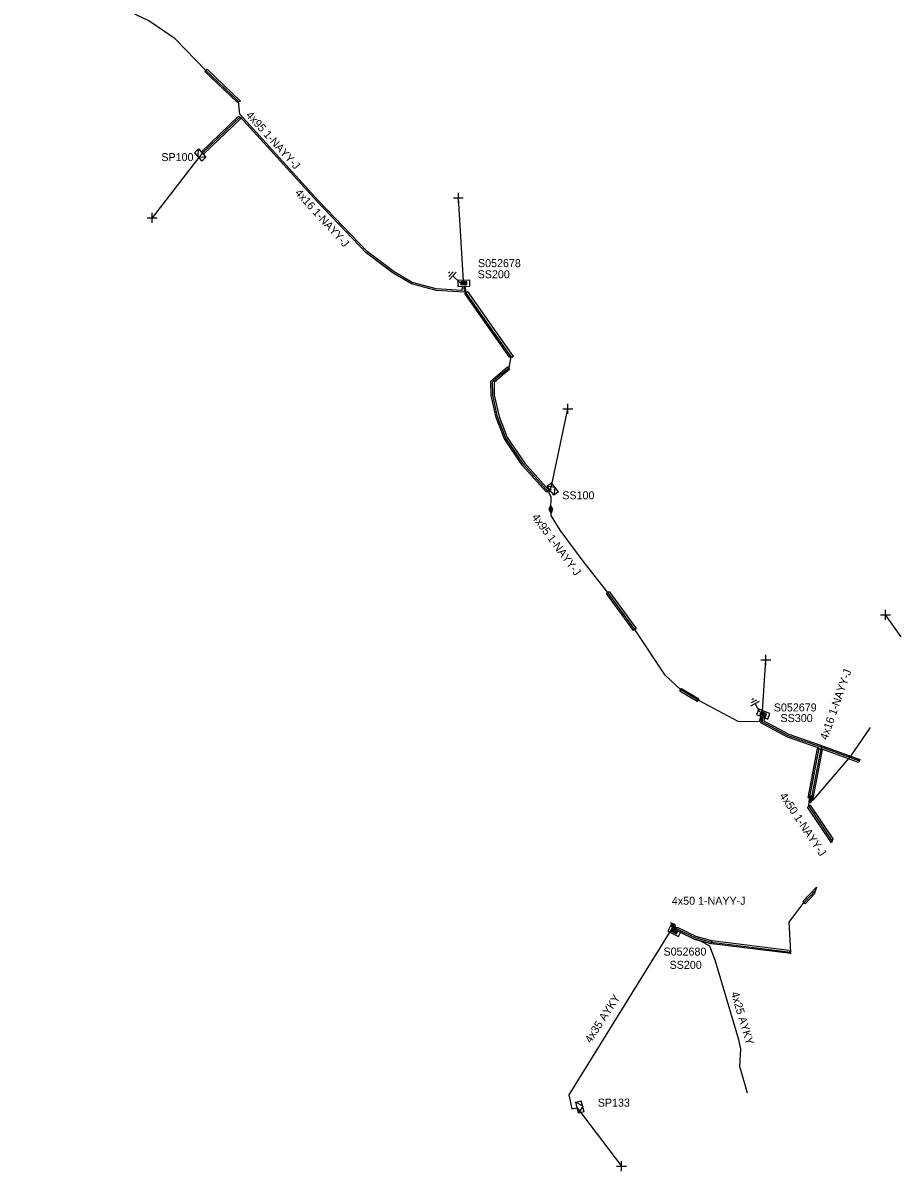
# Model space of a CAD drawing. Extents: x -717562 to -713845, y -1151196 to -1143903.
# Drawn here: x -714923 to -714813.3, y -1150441.1 to -1150297.7 of the extents above; entities that cross this region are included whole.
import ezdxf

# ---------------------------------------------------------------- set-up
doc = ezdxf.new("R2010")
doc.units = 0
for name, color, linetype in [('Vrstva 1', 7, 'Continuous'), ('Vrstva 14', 7, 'Continuous'), ('Vrstva 15', 7, 'Continuous'), ('Vrstva 19', 7, 'Continuous'), ('Vrstva 20', 7, 'Continuous'), ('Vrstva 28', 7, 'Continuous'), ('Vrstva 29', 7, 'Continuous'), ('Vrstva 30', 7, 'Continuous'), ('Vrstva 31', 7, 'Continuous'), ('Vrstva 33', 7, 'Continuous'), ('Vrstva 34', 7, 'Continuous'), ('Vrstva 4', 7, 'Continuous'), ('Vrstva 5', 7, 'Continuous'), ('Vrstva 52', 7, 'Continuous'), ('Vrstva 54', 7, 'Continuous'), ('Vrstva 59', 7, 'Continuous'), ('Vrstva 6', 7, 'Continuous'), ('Vrstva 8', 7, 'Continuous'), ('Vrstva 9', 7, 'Continuous')]:
    doc.layers.add(name, color=color, linetype=linetype)

# ---------------------------------------------------------------- blocks, each defined once
blk = doc.blocks.new('NN870')
at = {"layer": 'Vrstva 4'}
for points in [[(0, -0.25), (0.5, 0), (0, 0.25), (-0.5, 0), (0, -0.25)], [(0.37, 0), (0, 0.19), (-0.36, 0), (0, -0.19), (0.37, 0)], [(0.24, 0), (0, 0.12), (-0.25, 0), (0, -0.12), (0.24, 0)], [(0.12, 0), (0, 0.06), (-0.13, 0), (0, -0.06), (0.12, 0)]]:
    blk.add_lwpolyline(points, dxfattribs=at)
blk = doc.blocks.new('NN800')
at = {"layer": 'Vrstva 1'}
for points in [[(-0.44, 0.44), (0.44, -0.44)], [(-0.44, -0.44), (0.44, 0.44)]]:
    blk.add_lwpolyline(points, dxfattribs=at)
blk = doc.blocks.new('NN620')
at = {"layer": 'Vrstva 8'}
for points in [[(0.75, 0), (-0.75, 0)], [(-0.75, 0), (-0.75, -0.75)], [(0.75, -0.75), (0.75, 0)], [(-0.75, -0.75), (0.75, -0.75)], [(0.37, -0.18), (-0.38, -0.18)], [(-0.38, -0.18), (-0.38, -0.56)], [(-0.38, -0.56), (0.37, -0.56)], [(0.32, -0.23), (-0.33, -0.23)], [(-0.33, -0.23), (-0.33, -0.51)], [(-0.33, -0.51), (0.32, -0.51)], [(0.27, -0.27), (-0.28, -0.27)], [(-0.28, -0.27), (-0.28, -0.46)], [(-0.28, -0.46), (0.27, -0.46)], [(0.23, -0.32), (-0.23, -0.32)], [(-0.23, -0.32), (-0.23, -0.42)], [(-0.23, -0.42), (0.23, -0.42)], [(-0.19, -0.37), (0.19, -0.37)], [(0.23, -0.42), (0.23, -0.32)], [(0.27, -0.46), (0.27, -0.27)], [(0.32, -0.51), (0.32, -0.23)], [(0.37, -0.56), (0.37, -0.18)]]:
    blk.add_lwpolyline(points, dxfattribs=at)
blk = doc.blocks.new('NN630')
at = {"layer": 'Vrstva 9'}
for points in [[(0, -0.7), (-0.7, 0)], [(-0.7, -0.7), (-0.7, 0), (0.7, 0), (0.7, -0.7)], [(-0.7, -0.7), (0.7, -0.7)], [(0, -0.7), (0.7, 0)]]:
    blk.add_lwpolyline(points, dxfattribs=at)
blk = doc.blocks.new('NN810')
at = {"layer": 'Vrstva 14'}
for points in [[(0, -0.64), (0, -1.89)], [(0.63, -1.89), (-0.62, -1.89)], [(0.39, -2.2), (-0.4, -2.2)], [(0, -2.52), (-0.12, -2.52)], [(0.14, -2.52), (0, -2.52)]]:
    blk.add_lwpolyline(points, dxfattribs=at)

msp = doc.modelspace()

# ---------------------------------------------------------------- linework, layer by layer
at = {"layer": 'Vrstva 20'}
for points in [[(-714896.28, -1150307.57), (-714900.31, -1150303.72), (-714900.03, -1150303.43), (-714895.9, -1150307.39), (-714895.89, -1150307.46)], [(-714900.49, -1150314.06), (-714900.77, -1150313.78), (-714896.11, -1150309.31), (-714895.83, -1150309.6)], [(-714861.81, -1150339.42), (-714862.22, -1150339.42), (-714867.83, -1150331.45), (-714867.5, -1150331.22), (-714861.8, -1150339.33)], [(-714857.62, -1150356.29), (-714860.66, -1150352.91), (-714862.87, -1150349.62), (-714863.92, -1150346.95), (-714864.54, -1150344.19), (-714864.57, -1150342.41), (-714863.36, -1150341.37), (-714862.47, -1150340.64), (-714862.22, -1150340.95), (-714863.1, -1150341.67), (-714864.17, -1150342.59), (-714864.14, -1150344.15), (-714863.54, -1150346.83), (-714862.51, -1150349.44), (-714860.34, -1150352.67), (-714857.36, -1150355.98)], [(-714846.73, -1150373.56), (-714850.1, -1150368.94), (-714849.78, -1150368.7), (-714846.41, -1150373.33)], [(-714838.57, -1150382.1), (-714838.77, -1150382.44), (-714840.95, -1150381.15), (-714840.75, -1150380.81)], [(-714824.33, -1150394.58), (-714824.91, -1150394.47), (-714823.74, -1150388.32), (-714823.15, -1150388.43)], [(-714818.61, -1150390.06), (-714823.3, -1150388.37), (-714823.16, -1150388), (-714818.48, -1150389.69)], [(-714821.99, -1150400.09), (-714824.98, -1150395.65), (-714824.65, -1150395.42), (-714821.83, -1150399.62)], [(-714823.86, -1150405.63), (-714824.17, -1150406.54), (-714825.29, -1150407.73), (-714825.58, -1150407.46)], [(-714836.98, -1150412.32), (-714837.05, -1150412.72), (-714837.06, -1150412.72), (-714839.11, -1150412.14), (-714841.45, -1150411.03), (-714841.28, -1150410.67), (-714838.97, -1150411.76)], [(-714827.1, -1150413.96), (-714836.96, -1150412.73), (-714836.91, -1150412.33), (-714827.29, -1150413.53)]]:
    msp.add_lwpolyline(points, close=True, dxfattribs=at)
at = {"layer": 'Vrstva 5'}
for points in [[(-714868.14, -1150330.54), (-714868.18, -1150331.09), (-714871.39, -1150330.89), (-714874.42, -1150330.07), (-714876.67, -1150328.74), (-714880.02, -1150326.23), (-714886.1, -1150319.88), (-714895.94, -1150309.07), (-714896.09, -1150307.48), (-714900.21, -1150303.54), (-714904, -1150299.64), (-714907.29, -1150297.39), (-714912.07, -1150295.14), (-714918.82, -1150292.96), (-714923.04, -1150291.75)], [(-714830.83, -1150384.28), (-714831.02, -1150385), (-714833.65, -1150384.96), (-714838.67, -1150382.27), (-714840.88, -1150380.96), (-714842.77, -1150379.16), (-714846.57, -1150373.45), (-714849.94, -1150368.82), (-714852.91, -1150365.09), (-714855.9, -1150361.04), (-714857.03, -1150359.19), (-714857.09, -1150358.45), (-714857.02, -1150356.89), (-714857.32, -1150356.33), (-714857.11, -1150356.11), (-714857.43, -1150356.21), (-714860.5, -1150352.79), (-714862.69, -1150349.53), (-714863.73, -1150346.89), (-714864.34, -1150344.17), (-714864.37, -1150342.5), (-714863.23, -1150341.52), (-714862.29, -1150340.75), (-714862.01, -1150339.38), (-714867.68, -1150331.32), (-714867.75, -1150330.5)], [(-714821.91, -1150399.86), (-714824.85, -1150395.48), (-714824.73, -1150394.57), (-714823.53, -1150388.29), (-714827.48, -1150386.9), (-714830.85, -1150385.12), (-714830.67, -1150384.37)], [(-714818.55, -1150389.87), (-714823.49, -1150388.09), (-714827.4, -1150386.72), (-714830.65, -1150385), (-714830.53, -1150384.41)], [(-714830.39, -1150384.46), (-714830.47, -1150384.87), (-714827.32, -1150386.54), (-714823.26, -1150387.96), (-714824.53, -1150394.6)], [(-714841.16, -1150410.95), (-714839.04, -1150411.95), (-714837.02, -1150412.52), (-714827.08, -1150413.76), (-714827.3, -1150410.03), (-714825.54, -1150407.71), (-714824.01, -1150406.08)], [(-714841.59, -1150410.76), (-714841.58, -1150410.67), (-714841.76, -1150410.47)]]:
    msp.add_lwpolyline(points, dxfattribs=at)
at = {"layer": 'Vrstva 52'}
for points in [[(-714867.94, -1150330.55), (-714867.9, -1150331.31), (-714871.42, -1150331.09), (-714874.5, -1150330.26), (-714876.78, -1150328.91), (-714880.15, -1150326.38), (-714886.25, -1150320.02), (-714895.91, -1150309.4), (-714900.63, -1150313.92)], [(-714824.53, -1150394.6), (-714824.25, -1150394.74), (-714819.58, -1150389.29), (-714817.13, -1150385.68)], [(-714841.76, -1150410.47), (-714854.82, -1150431.6), (-714854.46, -1150433.36), (-714853.77, -1150433.21)], [(-714840.92, -1150411.28), (-714839.05, -1150412.17), (-714838.37, -1150412.36), (-714837.26, -1150412.98), (-714836.54, -1150414.85), (-714833.62, -1150424.69), (-714833.39, -1150425.88), (-714833.5, -1150428.03), (-714832.54, -1150431.36)]]:
    msp.add_lwpolyline(points, dxfattribs=at)
at = {"layer": 'Vrstva 59'}
for points in [[(-714900.63, -1150313.92), (-714906.88, -1150322)], [(-714867.98, -1150329.87), (-714868.63, -1150319.5)], [(-714857.11, -1150356.11), (-714854.94, -1150345.88)], [(-714813.31, -1150374.35), (-714815.25, -1150371.63)], [(-714830.62, -1150383.64), (-714830.19, -1150377.25)], [(-714853.77, -1150433.21), (-714848.25, -1150440.5)]]:
    msp.add_lwpolyline(points, dxfattribs=at)

# ---------------------------------------------------------------- block references
at = {"layer": 'Vrstva 15'}
for p, rotation in [((-714867.94, -1150330.55), -133.1741162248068), ((-714830.67, -1150384.37), -152.94376550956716)]:
    msp.add_blockref('NN810', p, dxfattribs=dict(at, rotation=rotation))
at = {"layer": 'Vrstva 19'}
for p, rotation in [((-714857.09, -1150358.45), -85.36453611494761), ((-714824.53, -1150394.6), 79.17845832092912), ((-714841.76, -1150410.47), -47.563769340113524)]:
    msp.add_blockref('NN870', p, dxfattribs=dict(at, rotation=rotation))
at = {"layer": 'Vrstva 28'}
for p, rotation in [((-714867.94, -1150330.55), -178.20121394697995), ((-714830.67, -1150384.37), 157.53621953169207), ((-714841.44, -1150410.82), -26.815411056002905)]:
    msp.add_blockref('NN620', p, dxfattribs=dict(at, rotation=rotation))
at = {"layer": 'Vrstva 31'}
for p, rotation in [((-714900.63, -1150313.92), -48.259344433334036), ((-714857.11, -1150356.11), 127.35578055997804), ((-714853.77, -1150433.21), 104.18085273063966)]:
    msp.add_blockref('NN630', p, dxfattribs=dict(at, rotation=rotation))
at = {"layer": 'Vrstva 34'}
for p, rotation in [((-714868.63, -1150319.5), 45), ((-714906.88, -1150322), 45), ((-714854.94, -1150345.88), 44.99999995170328), ((-714815.25, -1150371.63), 45), ((-714830.19, -1150377.25), 44.99999995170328), ((-714848.25, -1150440.5), 45)]:
    msp.add_blockref('NN800', p, dxfattribs=dict(at, rotation=rotation))

# ---------------------------------------------------------------- texts
at = {"layer": 'Vrstva 29'}
for s, p in [('S052678', (-714866.18, -1150328.17)), ('S052679', (-714829.21, -1150383.69)), ('S052680', (-714842.99, -1150414.2))]:
    msp.add_text(s, height=1, dxfattribs=at).set_placement(p)
at = {"layer": 'Vrstva 30'}
for s, p in [('SS200', (-714866.22, -1150329.56)), ('SS300', (-714828.37, -1150385.02)), ('SS200', (-714842.23, -1150415.86))]:
    msp.add_text(s, height=1, dxfattribs=at).set_placement(p)
at = {"layer": 'Vrstva 33'}
for s, p in [('SP100', (-714905.74, -1150314.92)), ('SS100', (-714855.64, -1150357.18)), ('SP133', (-714851.21, -1150433.08))]:
    msp.add_text(s, height=1, dxfattribs=at).set_placement(p)
at = {"layer": 'Vrstva 54'}
for s, rotation, p in [('4x16 1-NAYY-J', 312.29, (-714889.11, -1150318.95)), ('4x35 AYKY', 57.095, (-714852.08, -1150425.21)), ('4x25 AYKY', 286.528, (-714834.58, -1150418.87))]:
    msp.add_text(s, height=1, rotation=rotation, dxfattribs=at).set_placement(p)
at = {"layer": 'Vrstva 6'}
for s, rotation, p in [('4x95 1-NAYY-J', 312.289, (-714895.24, -1150309.23)), ('4x95 1-NAYY-J', 306.437, (-714859.5, -1150359.42)), ('4x16 1-NAYY-J', 70.689, (-714822.54, -1150387.33)), ('4x50 1-NAYY-J', 303.858, (-714828.55, -1150394.24))]:
    msp.add_text(s, height=1, rotation=rotation, dxfattribs=at).set_placement(p)
msp.add_text('4x50 1-NAYY-J', height=1, dxfattribs=at).set_placement((-714841.95, -1150407.85))

doc.saveas('drawing.dxf')
